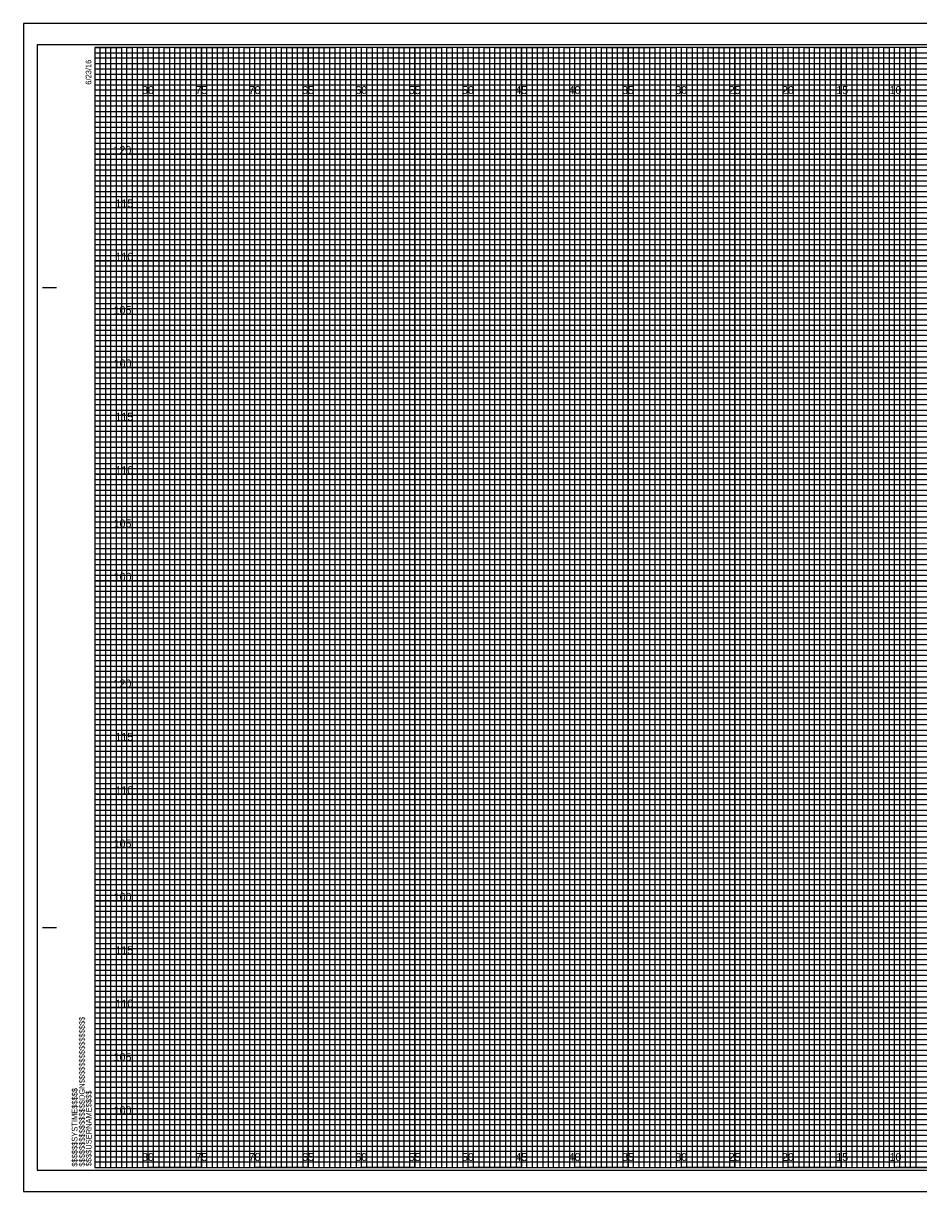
# Model space of a CAD drawing. Extents: x -7 to 182, y -2 to 1647.
# Drawn here: x -6.7 to 77.2, y 547.8 to 657.2 of the extents above; entities that cross this region are included whole.
import ezdxf

# ---------------------------------------------------------------- set-up
doc = ezdxf.new("R2010")
doc.units = 0
for name, color, linetype in [('Exist Cross Section Cell', 7, 'Continuous'), ('Exist XS Ground Line', 7, 'Continuous'), ('Prop CMT Pvmt Course 3', 7, 'Continuous'), ('Prop CMT Pvmt Wedge Surface 1', 7, 'Continuous'), ('Prop CMT Pvmt Wedge Surface 2', 7, 'Continuous'), ('Prop CMT Pvmt Wedge Surface 3', 7, 'Continuous'), ('Prop CMT Shld Paved Course 1', 7, 'Continuous'), ('Prop CMT Shld Paved Course 2', 7, 'Continuous'), ('Prop CMT Shld Paved Course 3', 7, 'Continuous'), ('Prop CMT Slope Grass', 7, 'Continuous'), ('Prop CMT Subgrade Earthwork', 7, 'Continuous')]:
    doc.layers.add(name, color=color, linetype=linetype)

msp = doc.modelspace()

# ---------------------------------------------------------------- linework, layer by layer
at = {"layer": 'Exist XS Ground Line'}
for p, q in [((5, 655), (0, 655)), ((5, 550), (5, 655)), ((15, 655), (10, 655)), ((10, 655), (10, 550)), ((15, 550), (15, 655)), ((25, 655), (20, 655)), ((20, 655), (20, 550)), ((25, 550), (25, 655)), ((35, 655), (30, 655)), ((30, 655), (30, 550)), ((35, 550), (35, 655)), ((45, 655), (40, 655)), ((40, 655), (40, 550)), ((45, 550), (45, 655)), ((55, 655), (50, 655)), ((50, 655), (50, 550)), ((55, 550), (55, 655)), ((65, 655), (60, 655)), ((60, 655), (60, 550)), ((65, 550), (65, 655)), ((75, 655), (70, 655)), ((70, 655), (70, 550)), ((75, 550), (75, 655)), ((10, 550), (5, 550)), ((20, 550), (15, 550)), ((30, 550), (25, 550)), ((40, 550), (35, 550)), ((50, 550), (45, 550)), ((60, 550), (55, 550)), ((70, 550), (65, 550)), ((80, 550), (75, 550))]:
    msp.add_line(p, q, dxfattribs=at)
for points in [[(0, 650), (160, 650), (160, 645), (0, 645)], [(0, 640), (160, 640), (160, 635), (0, 635)], [(0, 630), (160, 630), (160, 625), (0, 625)], [(0, 620), (160, 620), (160, 615), (0, 615)], [(0, 610), (160, 610), (160, 605), (0, 605)], [(0, 600), (160, 600), (160, 595), (0, 595)], [(0, 590), (160, 590), (160, 585), (0, 585)], [(0, 580), (160, 580), (160, 575), (0, 575)], [(0, 570), (160, 570), (160, 565), (0, 565)], [(0, 560), (160, 560), (160, 555), (0, 555)]]:
    msp.add_lwpolyline(points, dxfattribs=at)
at = {"layer": 'Prop CMT Pvmt Course 3'}
msp.add_lwpolyline([(-6.7, 547.75), (161.65, 547.75), (161.65, 657.25), (-6.7, 657.25)], close=True, dxfattribs=at)
at = {"layer": 'Prop CMT Pvmt Wedge Surface 1'}
for p, q in [((0, 654.5), (130, 654.5)), ((130, 653.99), (0, 653.99)), ((0, 653.99), (0, 653.5)), ((0, 653.5), (130, 653.5)), ((130, 652.95), (0, 652.95)), ((0, 652.95), (0, 652)), ((0, 652), (160, 652))]:
    msp.add_line(p, q, dxfattribs=at)
for points in [[(0, 651.5), (135, 651.5), (160, 651.5), (160, 651), (0, 651)], [(0, 650.5), (160, 650.5), (160, 649.5), (0, 649.5)], [(0, 649), (160, 649), (160, 648.5), (0, 648.49)], [(0, 648), (160, 648), (160, 647), (0, 647)], [(0, 646.5), (160, 646.5), (160, 646), (0, 646)], [(0, 645.5), (160, 645.5), (160, 644.5), (0, 644.5)], [(0, 644), (160, 644), (160, 643.5), (0, 643.5)], [(0, 643), (160, 643), (160, 642), (0, 642)], [(0, 641.5), (160, 641.5), (160, 641), (0, 641)], [(0, 640.5), (160, 640.5), (160, 639.5), (0, 639.5)], [(0, 639), (160, 639), (160, 638.5), (0, 638.5)], [(0, 638), (160, 638), (160, 636.98), (160, 636.5), (160, 636), (0, 636)], [(0, 637), (160, 637), (160, 636.5), (0, 636.5)], [(0, 635.5), (160, 635.5), (160, 634.5), (0, 634.51)], [(0, 634.51), (160, 634.5), (160, 634), (0, 634)], [(0, 633.5), (160, 633.5), (160, 633), (0, 633)], [(0, 632), (160, 632), (160, 631.5), (0, 631.5)], [(0, 631), (160, 631), (160, 630.5), (0, 630.5)], [(-0.04, 629.45), (160, 629.45), (160, 628.94), (-0.04, 628.94)], [(0, 628.5), (160, 628.5), (160, 628), (0, 628)], [(0, 627), (160, 627), (160, 626.5), (0, 626.5)], [(0, 626), (160, 626), (160, 625.5), (0, 625.5)], [(0, 624.5), (160, 624.5), (160, 624), (0, 624)], [(0, 623.5), (160, 623.5), (160, 623), (0, 623)], [(0, 622), (160, 622), (160, 621.5), (0, 621.5)], [(0, 621), (160, 621), (160, 620.5), (0, 620.5)], [(0, 619.5), (160, 619.5), (160, 618.99), (0, 619)], [(0, 618.5), (160, 618.5), (160, 618), (0, 618)], [(0, 617), (160, 617), (160, 616.5), (0, 616.5)], [(0, 616), (160, 616), (160, 615.5), (0, 615.5)], [(0, 614.5), (160, 614.5), (160, 614), (0, 614)], [(0, 613.5), (160, 613.5), (160, 613), (0, 613)], [(0, 612), (160, 612), (160, 611.5), (0, 611.5)], [(0, 611), (160, 611), (160, 610.5), (0, 610.5)], [(0, 609.5), (160, 609.5), (160, 609), (0, 609)], [(0, 608.5), (160.03, 608.46), (160, 608), (0, 608)], [(0, 607), (160, 607), (160, 606.5), (0, 606.5)], [(0, 606), (160, 606), (160, 605.5), (0, 605.5)], [(0, 604.5), (160, 604.5), (160, 604), (0, 604)], [(0, 603.5), (160, 603.5), (160, 603), (0, 603)], [(0, 602), (160, 602), (160, 601.5), (0, 601.5)], [(0, 601), (160, 601), (160, 600.5), (0, 600.5)], [(0, 599.5), (160, 599.5), (160, 599), (0, 599)], [(0, 598.5), (160, 598.5), (160, 598), (0, 598)], [(0, 597), (160, 597), (160, 596.5), (0, 596.5)], [(0, 596), (160, 596), (160, 595.5), (0, 595.5)], [(0, 594.5), (160, 594.5), (160, 594), (0, 594)], [(0, 593.5), (160, 593.5), (160, 593), (0, 593)], [(0, 592), (160, 592), (160, 591.5), (0, 591.5)], [(0, 591), (160, 591), (160, 590.5), (0, 590.5)], [(0, 589.5), (160, 589.5), (160, 588.99), (0, 589)], [(0, 588.5), (160, 588.5), (160, 588), (0, 588)], [(0, 587), (160, 587), (160, 586.5), (0, 586.5)], [(0, 586), (160, 586), (160, 585.5), (0, 585.5)], [(0, 584.5), (160, 584.5), (160, 584), (0, 584)], [(0, 583.5), (160, 583.5), (160, 583), (0, 583)], [(0, 582), (160, 582), (160, 581.5), (0, 581.5)], [(0, 581), (160, 581), (160, 580.5), (0, 580.5)], [(0, 579.5), (160, 579.5), (160, 579), (0, 579)], [(0, 578.5), (160.03, 578.46), (160, 578), (0, 578)], [(0, 577), (160, 577), (160, 576.5), (0, 576.5)], [(0, 576), (160, 576), (160, 575.5), (0, 575.5)], [(0, 574.5), (160, 574.5), (160, 574), (0, 574)], [(0, 573.5), (160, 573.5), (160, 573), (0, 573)], [(0, 572), (160, 572), (160, 571.5), (0, 571.5)], [(0, 571), (160, 571), (160, 570.5), (0, 570.5)], [(0, 569.5), (160, 569.5), (160, 569), (0, 569)], [(0, 568.5), (160, 568.5), (160, 568), (0, 568)], [(0, 567), (160, 567), (160, 566.5), (0, 566.5)], [(0, 566), (160, 566), (160, 565.5), (0, 565.5)], [(0, 564.5), (160, 564.5), (160, 564), (0, 564)], [(0, 563.5), (160, 563.5), (160, 563), (0, 563)], [(0, 562), (160, 562), (160, 561.5), (0, 561.5)], [(0, 561), (160, 561), (160, 560.5), (0, 560.5)], [(0, 559.5), (160, 559.5), (160, 559), (0, 559)], [(0, 558.5), (160, 558.5), (160, 558), (0, 558)], [(0, 557), (160, 557), (160, 556.5), (0, 556.5)], [(0, 556), (160, 556), (160, 555.5), (0, 555.5)], [(0, 554.5), (160, 554.5), (160, 554), (0, 554)], [(0, 553.5), (160, 553.5), (160, 553), (0, 553)], [(0, 552), (160, 552), (160, 551.5), (0, 551.5)], [(0, 551), (160, 551), (160, 550.5), (0, 550.5)]]:
    msp.add_lwpolyline(points, dxfattribs=at)
at = {"layer": 'Prop CMT Pvmt Wedge Surface 2'}
for p, q in [((-4.9, 632.5), (-3.65, 632.5)), ((-4.85, 632.5), (-3.6, 632.5)), ((-4.9, 572.5), (-3.65, 572.5)), ((-4.85, 572.5), (-3.6, 572.5)), ((0, 550), (0, 550)), ((0, 550), (0, 550)), ((0, 550), (0, 550)), ((0, 550), (0, 550)), ((0, 550), (0, 550)), ((0, 550), (0, 550)), ((0, 550), (0, 550))]:
    msp.add_line(p, q, dxfattribs=at)
msp.add_lwpolyline([(160, 655), (0, 655), (0, 550), (160, 550)], close=True, dxfattribs=at)
at = {"layer": 'Prop CMT Pvmt Wedge Surface 3'}
for points in [[(0, 550), (0.5, 550), (0.5, 655), (1, 655), (1, 550)], [(1, 550), (1.5, 550), (1.5, 655), (2, 655), (2, 550)], [(2.5, 550), (3, 550), (3, 655), (3.5, 655), (3.5, 550)], [(3.5, 550), (4, 550), (4, 655), (4.5, 655), (4.5, 550)], [(5, 550), (5.5, 550), (5.5, 655), (6, 655), (6, 550)], [(6, 550), (6.5, 550), (6.5, 655), (7, 655), (7, 550)], [(7.5, 550), (8, 550), (8, 655), (8.5, 655), (8.5, 550)], [(8.5, 550), (9, 550), (9, 655), (9.5, 655), (9.5, 550)], [(10, 550), (10.5, 550), (10.5, 655), (11, 655), (11, 550)], [(11, 550), (11.5, 550), (11.5, 655), (12, 655), (12, 550)], [(12.5, 550), (13, 550), (13, 655), (13.5, 655), (13.5, 550)], [(13.5, 550), (14, 550), (14, 655), (14.5, 655), (14.5, 550)], [(15, 550), (15.5, 550), (15.5, 655), (16, 655), (16, 550)], [(16, 550), (16.5, 550), (16.5, 655), (17, 655), (17, 550)], [(17.5, 550), (18, 550), (18, 655), (18.5, 655), (18.5, 550)], [(18.5, 550), (19, 550), (19, 655), (19.5, 655), (19.5, 550)], [(20, 550), (20.5, 550), (20.5, 655), (21, 655), (21, 550)], [(21, 550), (21.5, 550), (21.5, 655), (22, 655), (22, 550)], [(22.5, 550), (23, 550), (23, 655), (23.5, 655), (23.5, 550)], [(23.5, 550), (24, 550), (24, 655), (24.5, 655), (24.5, 550)], [(25, 550), (25.5, 550), (25.5, 655), (26, 655), (26, 550)], [(26, 550), (26.5, 550), (26.5, 655), (27, 655), (27, 550)], [(27.5, 550), (28, 550), (28, 655), (28.5, 655), (28.5, 550)], [(28.5, 550), (29, 550), (29, 655), (29.5, 655), (29.5, 550)], [(30, 550), (30.5, 550), (30.5, 655), (31, 655), (31, 550)], [(31, 550), (31.5, 550), (31.5, 655), (32, 655), (32, 550)], [(32.5, 550), (33, 550), (33, 655), (33.5, 655), (33.5, 550)], [(33.5, 550), (34, 550), (34, 655), (34.5, 655), (34.5, 550)], [(35, 550), (35.5, 550), (35.5, 655), (36, 655), (36, 550)], [(36, 550), (36.5, 550), (36.5, 655), (37, 655), (37, 550)], [(37.5, 550), (38, 550), (38, 655), (38.5, 655), (38.5, 550)], [(38.5, 550), (39, 550), (39, 655), (39.5, 655), (39.5, 550)], [(40, 550), (40.5, 550), (40.5, 655), (41, 655), (41, 550)], [(41, 550), (41.5, 550), (41.5, 655), (42, 655), (42, 550)], [(42.5, 550), (43, 550), (43, 655), (43.5, 655), (43.5, 550)], [(43.5, 550), (44, 550), (44, 655), (44.5, 655), (44.5, 550)], [(45, 550), (45.5, 550), (45.5, 655), (46, 655), (46, 550)], [(46, 550), (46.5, 550), (46.5, 655), (47, 655), (47, 550)], [(47.5, 550), (48, 550), (48, 655), (48.5, 655), (48.5, 550)], [(48.5, 550), (49, 550), (49, 655), (49.5, 655), (49.5, 550)], [(50, 550), (50.5, 550), (50.5, 655), (51, 655), (51, 550)], [(51, 550), (51.5, 550), (51.5, 655), (52, 655), (52, 550)], [(52.5, 550), (53, 550), (53, 655), (53.5, 655), (53.5, 550)], [(53.5, 550), (54, 550), (54, 655), (54.5, 655), (54.5, 550)], [(55, 550), (55.5, 550), (55.5, 655), (56, 655), (56, 550)], [(56, 550), (56.5, 550), (56.5, 655), (57, 655), (57, 550)], [(57.5, 550), (58, 550), (58, 655), (58.5, 655), (58.5, 550)], [(58.5, 550), (59, 550), (59, 655), (59.5, 655), (59.5, 550)], [(60, 550), (60.5, 550), (60.5, 655), (61, 655), (61, 550)], [(61, 550), (61.5, 550), (61.5, 655), (62, 655), (62, 550)], [(62.5, 550), (63, 550), (63, 655), (63.5, 655), (63.5, 550)], [(63.5, 550), (64, 550), (64, 655), (64.5, 655), (64.5, 550)], [(65, 550), (65.5, 550), (65.5, 655), (66, 655), (66, 550)], [(66, 550), (66.5, 550), (66.5, 655), (67, 655), (67, 550)], [(67.5, 550), (68, 550), (68, 655), (68.5, 655), (68.5, 550)], [(68.5, 550), (69, 550), (69, 655), (69.5, 655), (69.5, 550)], [(70, 550), (70.5, 550), (70.5, 655), (71, 655), (71, 550)], [(71, 550), (71.5, 550), (71.5, 655), (72, 655), (72, 550)], [(72.5, 550), (73, 550), (73, 655), (73.5, 655), (73.5, 550)], [(73.5, 550), (74, 550), (74, 655), (74.5, 655), (74.5, 550)], [(75, 550), (75.5, 550), (75.5, 655), (76, 655), (76, 550)], [(76, 550), (76.5, 550), (76.5, 655), (77, 655), (77, 550)]]:
    msp.add_lwpolyline(points, dxfattribs=at)
at = {"layer": 'Prop CMT Shld Paved Course 1'}
for p, q in [((5, 550), (5, 655)), ((10, 550), (10, 655)), ((15, 550), (15, 655)), ((20, 550), (20, 655)), ((25, 550), (25, 655)), ((30, 550), (30, 655)), ((35, 550), (35, 655)), ((40, 550), (40, 655)), ((45, 550), (45, 655)), ((50, 550), (50, 655)), ((55, 550), (55, 655)), ((60, 550), (60, 655)), ((65, 550), (65, 655)), ((70, 550), (70, 655)), ((75, 550), (75, 655)), ((0, 650), (160, 650)), ((0, 645), (160, 645)), ((0, 640), (160, 640)), ((0, 635), (160, 635)), ((0, 630), (160, 630)), ((0, 625), (160, 625)), ((0, 620), (160, 620)), ((0, 615), (160, 615)), ((0, 610), (160, 610)), ((0, 605), (160, 605)), ((0, 600), (160, 600)), ((0, 595), (160, 595)), ((0, 590), (160, 590)), ((0, 585), (160, 585)), ((0, 580), (160, 580)), ((0, 575), (160, 575)), ((0, 570), (160, 570)), ((0, 565), (160, 565)), ((0, 560), (160, 560)), ((0, 555), (160, 555))]:
    msp.add_line(p, q, dxfattribs=at)
at = {"layer": 'Prop CMT Shld Paved Course 2'}
for p, q in [((161.65, 657.25), (-6.7, 657.25)), ((-6.7, 657.25), (-6.7, 547.75)), ((-6.7, 547.75), (161.65, 547.75))]:
    msp.add_line(p, q, dxfattribs=at)
at = {"layer": 'Prop CMT Slope Grass'}
msp.add_lwpolyline([(-5.4, 549.75), (161.2, 549.75), (161.2, 655.25), (-5.4, 655.25)], close=True, dxfattribs=at)
at = {"layer": 'Prop CMT Subgrade Earthwork'}
for points in [[(0, 655), (2.5, 655), (2.5, 550), (7.5, 550), (7.5, 655), (12.5, 655), (12.5, 550), (17.5, 550), (17.5, 655), (22.5, 655), (22.5, 550), (27.5, 550), (27.5, 655), (32.5, 655), (32.5, 550), (37.5, 550), (37.5, 655), (42.5, 655), (42.5, 550), (47.5, 550), (47.5, 655), (52.5, 655), (52.5, 550), (57.5, 550), (57.5, 655), (62.5, 655), (62.5, 550), (67.5, 550), (67.5, 655), (72.5, 655), (72.5, 550), (77.5, 550)], [(0, 652.5), (137.5, 652.5)], [(0, 642.5), (160, 642.5), (160, 647.5), (0, 647.5)], [(0, 632.5), (160, 632.5), (160, 637.5), (0, 637.5)], [(0, 622.5), (160, 622.5), (160, 627.5), (0, 627.5)], [(0, 612.5), (160, 612.5), (160, 617.5), (0, 617.5)], [(0, 602.5), (160, 602.5), (160, 607.5), (0, 607.5)], [(0, 592.5), (160, 592.5), (160, 597.5), (0, 597.5)], [(0, 582.5), (160, 582.5), (160, 587.5), (0, 587.5)], [(0, 572.5), (160, 572.5), (160, 577.5), (0, 577.5)], [(0, 562.5), (160, 562.5), (160, 567.5), (0, 567.5)], [(0, 552.5), (160, 552.5), (160, 557.5), (0, 557.5)]]:
    msp.add_lwpolyline(points, dxfattribs=at)

# ---------------------------------------------------------------- texts
at = {"layer": 'Exist Cross Section Cell'}
for s, p in [('80', (4.43, 650.62)), ('75', (9.44, 650.62)), ('70', (14.43, 650.62)), ('65', (19.44, 650.62)), ('60', (24.43, 650.62)), ('55', (29.44, 650.62)), ('50', (34.43, 650.62)), ('45', (39.44, 650.62)), ('40', (44.43, 650.62)), ('35', (49.44, 650.62)), ('30', (54.43, 650.62)), ('25', (59.44, 650.62)), ('20', (64.43, 650.62)), ('15', (69.53, 650.62)), ('10', (74.52, 650.62)), ('80', (4.43, 550.62)), ('75', (9.44, 550.62)), ('70', (14.43, 550.62)), ('65', (19.44, 550.62)), ('60', (24.43, 550.62)), ('55', (29.44, 550.62)), ('50', (34.43, 550.62)), ('45', (39.44, 550.62)), ('40', (44.43, 550.62)), ('35', (49.44, 550.62)), ('30', (54.43, 550.62)), ('25', (59.44, 550.62)), ('20', (64.43, 550.62)), ('15', (69.53, 550.62)), ('10', (74.52, 550.62))]:
    msp.add_text(s, height=0.75, dxfattribs=at).set_placement(p)
at = {"layer": 'Prop CMT Pvmt Wedge Surface 2'}
for s, p in [('6/23/16', (-0.33, 651.5)), ('$$$$$$$$$$$$$$$$DGN$$$$$$$$$$$$$$$$', (-0.94, 550.09)), ('$$$$$$SYSTIME$$$$$', (-1.63, 550.09)), ('$$$$USERNAME$$$$', (-0.31, 550.12))]:
    msp.add_text(s, height=0.525, rotation=90, dxfattribs=at).set_placement(p)
at = {"layer": 'Prop CMT Shld Paved Course 3'}
for s, p in [('120', (1.75, 645)), ('115', (1.93, 640)), ('110', (1.94, 635)), ('105', (1.76, 630)), ('100', (1.77, 625)), ('115', (1.93, 620)), ('110', (1.94, 615)), ('105', (1.76, 610)), ('100', (1.77, 605)), ('120', (1.75, 595)), ('115', (1.93, 590)), ('110', (1.94, 585)), ('105', (1.76, 580)), ('100', (1.77, 575)), ('115', (1.93, 570)), ('110', (1.94, 565)), ('105', (1.76, 560)), ('100', (1.77, 555))]:
    msp.add_text(s, height=0.75, dxfattribs=at).set_placement(p)

doc.saveas('drawing.dxf')
